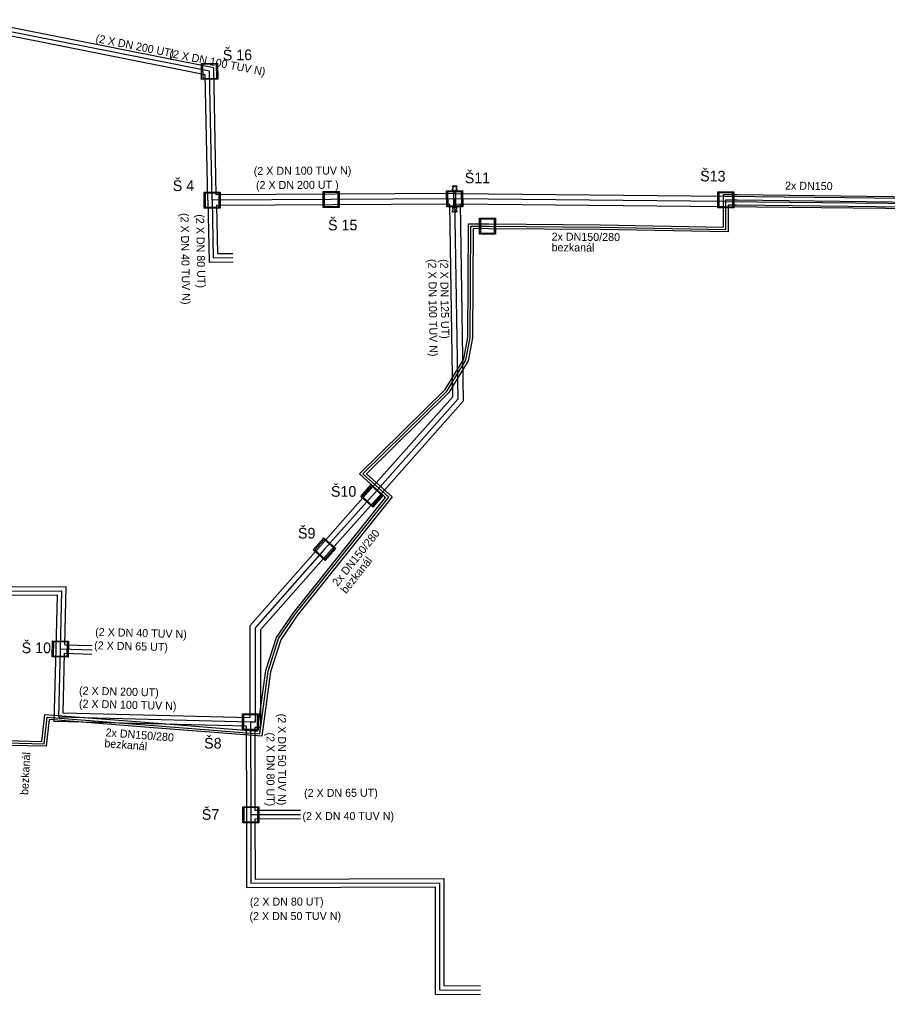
# Model space of a CAD drawing. Extents: x -606118 to -604472, y -1157869 to -1156854.
# Drawn here: x -605302 to -605139.3, y -1157347 to -1157164.2 of the extents above; entities that cross this region are included whole.
import ezdxf

# ---------------------------------------------------------------- set-up
doc = ezdxf.new("R2010")
doc.units = 0
for name, color, linetype in [('Osa trasy teplovodu', 7, 'Continuous'), ('označení šachty', 7, 'Continuous'), ('Pevný bod trasy teplovodu', 7, 'Continuous'), ('Teplovod - trasa - okraj', 7, 'Continuous'), ('Teplovod - trasa popis', 7, 'Continuous'), ('Teplovod - trasa popis 2', 7, 'Continuous'), ('Šachta trasy teplovodu', 7, 'Continuous')]:
    doc.layers.add(name, color=color, linetype=linetype)

msp = doc.modelspace()

# ---------------------------------------------------------------- linework, layer by layer
at = {"layer": 'Osa trasy teplovodu'}
for p, q in [((-605169.85, -1157198.38), (-605220.42, -1157197.86)), ((-605235.91, -1157253.53), (-605244.79, -1157263.54)), ((-605294.3, -1157282.23), (-605288.37, -1157282.38)), ((-605258.66, -1157295.93), (-605258.64, -1157313.26)), ((-605258.64, -1157313.26), (-605249.34, -1157313.23))]:
    msp.add_line(p, q, dxfattribs=at)
for points in [[(-605265.88, -1157198.1), (-605266.36, -1157173.94), (-605311.27, -1157165.05)], [(-605220.42, -1157197.86), (-605243.55, -1157197.98), (-605265.88, -1157198.1)], [(-605265.88, -1157198.1), (-605265.66, -1157208.94), (-605261.96, -1157208.88)], [(-605220.42, -1157197.86), (-605219.84, -1157235.42), (-605235.91, -1157253.53)], [(-605213.99, -1157203.01), (-605193.06, -1157203.16), (-605169.63, -1157203.61), (-605169.6, -1157198.05)], [(-605169.85, -1157198.38), (-605114.56, -1157198.95), (-605114.57, -1157202.26), (-605112.73, -1157202.28), (-605112.71, -1157198.97), (-605077.45, -1157199.34)], [(-605169.6, -1157198.05), (-605167.51, -1157198.07), (-605114.32, -1157198.71), (-605114.34, -1157202.16), (-605113.1, -1157202.17), (-605113.05, -1157198.72), (-605102.26, -1157198.85), (-605083.64, -1157199.07), (-605082.78, -1157199.08), (-605078.61, -1157199.08)], [(-605304.37, -1157299.84), (-605297.36, -1157300.01), (-605296.8, -1157294.99), (-605276.88, -1157296.55), (-605256.95, -1157298.11), (-605255.35, -1157286.4), (-605253.42, -1157280.3), (-605250.29, -1157275.7), (-605232.75, -1157253.79), (-605237.62, -1157249.41), (-605229.75, -1157241.65), (-605221.88, -1157233.89), (-605218.3, -1157228.07), (-605217.5, -1157223.86), (-605217.44, -1157213.42), (-605217.38, -1157202.98), (-605214.26, -1157203.01), (-605214.26, -1157203.01), (-605213.99, -1157203.01)], [(-605244.79, -1157263.54), (-605257.83, -1157278.25), (-605257.81, -1157295.95), (-605258.66, -1157295.93)], [(-605294.3, -1157282.23), (-605294.04, -1157271.38), (-605343.03, -1157271.52)], [(-605258.66, -1157295.93), (-605294.62, -1157295.03), (-605294.3, -1157282.23)], [(-605258.64, -1157313.3), (-605258.63, -1157326.16), (-605223.25, -1157326.04), (-605223.27, -1157346.14), (-605215.57, -1157346.2)]]:
    msp.add_lwpolyline(points, dxfattribs=at)
at = {"layer": 'Pevný bod trasy teplovodu'}
msp.add_lwpolyline([(-605220.57, -1157196.16), (-605220.7, -1157196.29), (-605220.71, -1157196.29), (-605220.89, -1157196.06), (-605220.63, -1157195.8), (-605220.89, -1157195.54), (-605220.89, -1157195.53), (-605220.66, -1157195.35), (-605220.42, -1157195.59), (-605220.18, -1157195.35), (-605219.96, -1157195.54), (-605220.21, -1157195.8), (-605219.96, -1157196.06), (-605220.14, -1157196.29), (-605220.26, -1157196.17), (-605220.26, -1157199.5), (-605220.18, -1157199.42), (-605219.96, -1157199.61), (-605220.21, -1157199.87), (-605219.96, -1157200.12), (-605220.14, -1157200.35), (-605220.42, -1157200.08), (-605220.7, -1157200.36), (-605220.71, -1157200.36), (-605220.89, -1157200.13), (-605220.63, -1157199.87), (-605220.89, -1157199.6), (-605220.89, -1157199.6), (-605220.66, -1157199.42), (-605220.57, -1157199.51), (-605220.57, -1157196.16)], dxfattribs=at)
at = {"layer": 'Teplovod - trasa - okraj'}
for p, q in [((-605220.43, -1157196.86), (-605265.1, -1157197.1)), ((-605220.41, -1157196.86), (-605169.84, -1157197.38)), ((-605221.41, -1157198.86), (-605265.06, -1157199.1)), ((-605169.86, -1157199.38), (-605220.43, -1157198.86)), ((-605236.66, -1157252.87), (-605245.53, -1157262.88)), ((-605235.16, -1157254.2), (-605244.04, -1157264.21)), ((-605293.48, -1157281.45), (-605288.35, -1157281.58)), ((-605293.52, -1157283.05), (-605288.39, -1157283.18)), ((-605259.46, -1157296.71), (-605259.44, -1157313.26)), ((-605257.86, -1157296.95), (-605257.84, -1157312.46)), ((-605257.84, -1157312.46), (-605249.34, -1157312.43)), ((-605257.84, -1157314.06), (-605249.34, -1157314.03))]:
    msp.add_line(p, q, dxfattribs=at)
for points in [[(-605265.1, -1157197.1), (-605265.57, -1157173.28), (-605311.19, -1157164.25)], [(-605266.68, -1157198.12), (-605267.15, -1157174.6), (-605310.46, -1157166.02)], [(-605213.99, -1157202.56), (-605193.06, -1157202.71), (-605170.07, -1157203.15), (-605170.04, -1157197.05)], [(-605170.04, -1157197.05), (-605167.5, -1157197.07), (-605114.03, -1157197.71), (-605114.03, -1157197.7), (-605102.25, -1157197.85), (-605083.63, -1157198.07), (-605082.78, -1157198.08), (-605079.06, -1157198.08)], [(-605169.84, -1157197.38), (-605113.71, -1157197.96), (-605113.71, -1157197.96), (-605078.98, -1157198.32)], [(-605266.68, -1157198.12), (-605266.44, -1157209.75), (-605261.95, -1157209.68)], [(-605265.06, -1157199.1), (-605264.88, -1157208.12), (-605261.97, -1157208.08)], [(-605221.41, -1157198.86), (-605220.85, -1157235.05), (-605236.66, -1157252.87)], [(-605219.41, -1157198.87), (-605218.84, -1157235.8), (-605235.16, -1157254.2)], [(-605169.15, -1157199.06), (-605169.18, -1157204.07), (-605193.07, -1157203.61), (-605213.99, -1157203.46)], [(-605078.17, -1157200.08), (-605082.79, -1157200.08), (-605083.65, -1157200.07), (-605102.27, -1157199.85), (-605112.06, -1157199.73), (-605112.11, -1157203.19), (-605115.35, -1157203.14), (-605115.32, -1157199.69), (-605167.52, -1157199.07), (-605169.15, -1157199.06)], [(-605078.23, -1157200.33), (-605111.72, -1157199.98), (-605111.74, -1157203.28), (-605115.57, -1157203.25), (-605115.56, -1157199.94), (-605169.86, -1157199.38)], [(-605304.36, -1157299.39), (-605297.76, -1157299.55), (-605297.2, -1157294.51), (-605276.84, -1157296.1), (-605257.34, -1157297.62), (-605255.79, -1157286.3), (-605253.83, -1157280.1), (-605250.65, -1157275.44), (-605233.37, -1157253.84), (-605238.28, -1157249.43), (-605222.23, -1157233.61), (-605218.73, -1157227.91), (-605217.95, -1157223.82), (-605217.89, -1157213.42), (-605217.83, -1157202.53), (-605213.99, -1157202.56)], [(-605213.99, -1157203.46), (-605216.94, -1157203.44), (-605216.99, -1157213.42), (-605217.05, -1157223.9), (-605217.87, -1157228.24), (-605221.52, -1157234.17), (-605236.97, -1157249.4), (-605232.14, -1157253.74), (-605249.93, -1157275.97), (-605253.01, -1157280.5), (-605254.91, -1157286.49), (-605256.57, -1157298.59), (-605276.91, -1157297), (-605296.4, -1157295.47), (-605296.96, -1157300.47), (-605304.09, -1157300.3)], [(-605245.53, -1157262.88), (-605258.83, -1157277.87), (-605258.81, -1157295.12)], [(-605244.04, -1157264.21), (-605256.83, -1157278.63), (-605256.81, -1157296.97), (-605257.86, -1157296.95)], [(-605295.1, -1157282.21), (-605294.86, -1157272.18), (-605343.83, -1157272.32)], [(-605293.48, -1157281.45), (-605293.22, -1157270.58), (-605343.04, -1157270.72)], [(-605259.46, -1157296.71), (-605295.44, -1157295.81), (-605295.1, -1157282.21)], [(-605258.81, -1157295.12), (-605293.8, -1157294.25), (-605293.52, -1157283.05)], [(-605259.44, -1157313.3), (-605259.43, -1157326.96), (-605224.05, -1157326.85), (-605224.07, -1157346.93), (-605215.57, -1157347)], [(-605257.84, -1157314.06), (-605257.83, -1157325.36), (-605222.45, -1157325.24), (-605222.47, -1157345.34), (-605215.56, -1157345.4)]]:
    msp.add_lwpolyline(points, dxfattribs=at)
at = {"layer": 'Šachta trasy teplovodu'}
for points in [[(-605267.89, -1157172.47), (-605264.88, -1157172.41), (-605264.82, -1157175.41), (-605267.83, -1157175.47), (-605267.89, -1157172.47)], [(-605267.64, -1157175.28), (-605265.01, -1157175.23), (-605265.07, -1157172.6), (-605267.7, -1157172.65), (-605267.64, -1157175.28)], [(-605267.37, -1157199.61), (-605267.39, -1157196.6), (-605264.38, -1157196.59), (-605264.37, -1157199.59), (-605267.37, -1157199.61)], [(-605264.55, -1157199.41), (-605264.57, -1157196.78), (-605267.2, -1157196.79), (-605267.18, -1157199.42), (-605264.55, -1157199.41)], [(-605245.05, -1157199.49), (-605245.06, -1157196.48), (-605242.06, -1157196.47), (-605242.04, -1157199.47), (-605245.05, -1157199.49)], [(-605242.23, -1157199.29), (-605242.24, -1157196.66), (-605244.87, -1157196.67), (-605244.86, -1157199.3), (-605242.23, -1157199.29)], [(-605221.95, -1157196.38), (-605218.94, -1157196.33), (-605218.89, -1157199.34), (-605221.9, -1157199.39), (-605221.95, -1157196.38)], [(-605221.72, -1157199.19), (-605219.09, -1157199.15), (-605219.13, -1157196.52), (-605221.76, -1157196.56), (-605221.72, -1157199.19)], [(-605171.12, -1157199.54), (-605171.09, -1157196.53), (-605168.08, -1157196.56), (-605168.11, -1157199.57), (-605171.12, -1157199.54)], [(-605168.3, -1157199.38), (-605168.27, -1157196.75), (-605170.9, -1157196.72), (-605170.93, -1157199.35), (-605168.3, -1157199.38)], [(-605215.76, -1157204.51), (-605215.76, -1157201.5), (-605212.76, -1157201.5), (-605212.76, -1157204.51), (-605215.76, -1157204.51)], [(-605212.95, -1157204.32), (-605212.95, -1157201.69), (-605215.58, -1157201.69), (-605215.58, -1157204.32), (-605212.95, -1157204.32)], [(-605235.78, -1157255.65), (-605238.03, -1157253.66), (-605236.04, -1157251.41), (-605233.79, -1157253.41), (-605235.78, -1157255.65)], [(-605234.05, -1157253.42), (-605236.02, -1157251.68), (-605237.77, -1157253.64), (-605235.8, -1157255.39), (-605234.05, -1157253.42)], [(-605244.66, -1157265.66), (-605246.91, -1157263.67), (-605244.91, -1157261.42), (-605242.67, -1157263.42), (-605244.66, -1157265.66)], [(-605242.93, -1157263.43), (-605244.9, -1157261.69), (-605246.64, -1157263.65), (-605244.68, -1157265.4), (-605242.93, -1157263.43)], [(-605292.84, -1157283.77), (-605295.85, -1157283.7), (-605295.77, -1157280.69), (-605292.77, -1157280.77), (-605292.84, -1157283.77)], [(-605292.96, -1157280.95), (-605295.59, -1157280.89), (-605295.65, -1157283.51), (-605293.02, -1157283.58), (-605292.96, -1157280.95)], [(-605260.16, -1157294.42), (-605257.15, -1157294.42), (-605257.15, -1157297.43), (-605260.16, -1157297.43), (-605260.16, -1157294.42)], [(-605259.97, -1157297.24), (-605257.34, -1157297.24), (-605257.34, -1157294.61), (-605259.97, -1157294.61), (-605259.97, -1157297.24)], [(-605260.14, -1157311.8), (-605257.14, -1157311.8), (-605257.14, -1157314.8), (-605260.14, -1157314.8), (-605260.14, -1157311.8)], [(-605259.95, -1157314.62), (-605257.32, -1157314.61), (-605257.32, -1157311.98), (-605259.95, -1157311.99), (-605259.95, -1157314.62)]]:
    msp.add_lwpolyline(points, dxfattribs=at)

# ---------------------------------------------------------------- texts
at = {"layer": 'označení šachty'}
for s, rotation, p in [('Š 16', 0.6303, (-605263.86, -1157171.92)), ('Š13', 359.4164, (-605174.43, -1157194.58))]:
    msp.add_text(s, height=2, rotation=rotation, dxfattribs=at).set_placement(p)
for s, p in [('Š11', (-605218.53, -1157194.94)), ('Š 4', (-605273.24, -1157196.39)), ('Š 15', (-605244.15, -1157203.77)), ('Š10', (-605243.61, -1157253.7)), ('Š9', (-605249.78, -1157261.53)), ('Š 10', (-605301.56, -1157283.02)), ('Š8', (-605267.37, -1157300.9)), ('Š7', (-605267.8, -1157314.26))]:
    msp.add_text(s, height=2, dxfattribs=at).set_placement(p)
at = {"layer": 'Teplovod - trasa popis'}
for s, rotation, p in [('(2 X DN 200 UT)', 348.8167, (-605287.8, -1157168.47)), ('(2 X DN 200 UT )', 0.2865, (-605257.65, -1157196.04)), ('2x DN150', 359.3189, (-605158.52, -1157196.13)), ('(2 X DN 80 UT)', 271.1236, (-605268.88, -1157200.77)), ('2x DN150/280', 359.5713, (-605202.26, -1157205.69)), ('(2 X DN 125 UT)', 270.8944, (-605223.15, -1157209.17)), ('2x DN150/280', 51.3364, (-605242.35, -1157270.6)), ('(2 X DN 65 UT)', 358.557, (-605287.99, -1157282.29)), ('(2 X DN 200 UT)', 358.557, (-605290.82, -1157290.77)), ('2x DN150/280', 355.5259, (-605285.88, -1157298.59)), ('(2 X DN 80 UT)', 270.035, (-605255.68, -1157297.89)), ('(2 X DN 65 UT)', 0.1719, (-605248.64, -1157309.97)), ('(2 X DN 80 UT)', 0.1719, (-605258.8, -1157330.36))]:
    msp.add_text(s, height=1.5, rotation=rotation, dxfattribs=at).set_placement(p)
at = {"layer": 'Teplovod - trasa popis 2'}
for s, rotation, p in [('(2 X DN 100 TUV N)', 348.8167, (-605273.98, -1157171.27)), ('(2 X DN 100 TUV N)', 0.2865, (-605258.07, -1157193.38)), ('(2 X DN 40 TUV N)', 271.1236, (-605271.8, -1157200.53)), ('bezkanál', 359.5713, (-605202.26, -1157207.69)), ('(2 X DN 100 TUV N)', 270.8831, (-605225.39, -1157209.15)), ('bezkanál', 51.3364, (-605240.76, -1157271.97)), ('(2 X DN 40 TUV N)', 358.557, (-605287.79, -1157279.78)), ('(2 X DN 100 TUV N)', 358.557, (-605290.84, -1157293.21)), ('(2 X DN 50 TUV N)', 270.035, (-605253.54, -1157294.37)), ('bezkanál', 355.5259, (-605286.11, -1157300.63)), ('bezkanál', 87.0645, (-605300.34, -1157309.63)), ('(2 X DN 40 TUV N)', 0.1719, (-605248.94, -1157314.31)), ('(2 X DN 50 TUV N)', 0.1719, (-605258.87, -1157333.07))]:
    msp.add_text(s, height=1.5, rotation=rotation, dxfattribs=at).set_placement(p)

doc.saveas('drawing.dxf')
